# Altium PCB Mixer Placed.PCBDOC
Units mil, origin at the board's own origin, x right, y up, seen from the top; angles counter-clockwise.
Board outline 8000 x 4000 mil, 2 copper layers (Top Layer, Bottom Layer); 97 components, 56 nets, 281 pads, 0 vias.
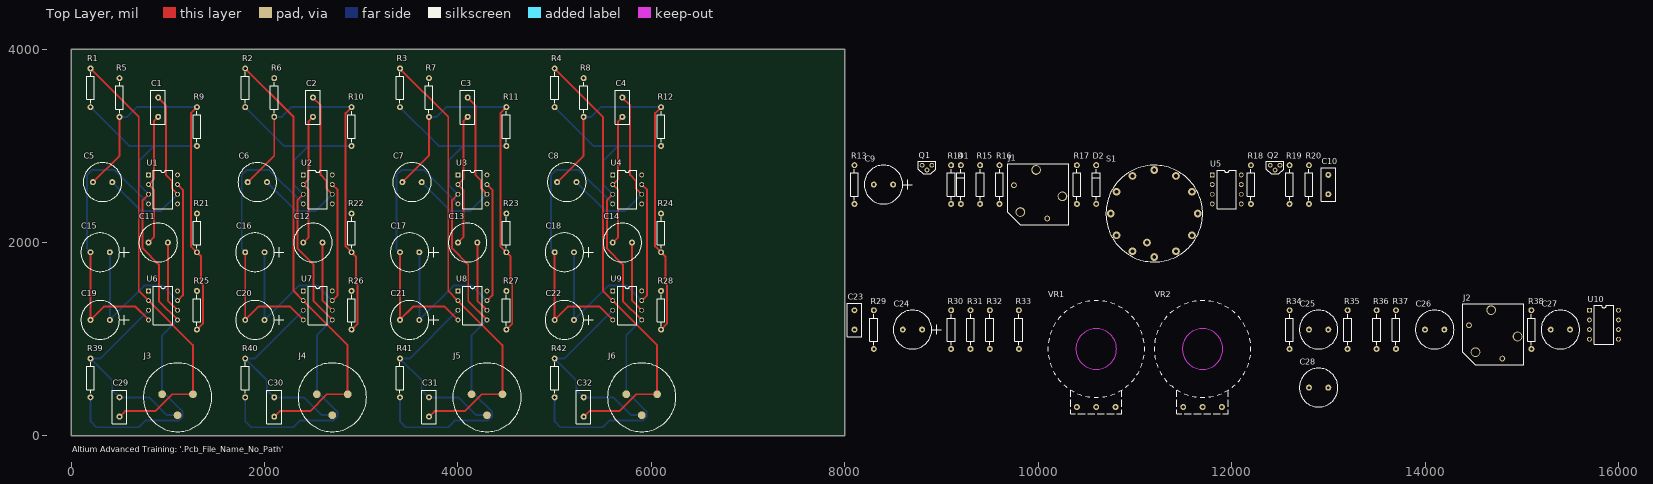
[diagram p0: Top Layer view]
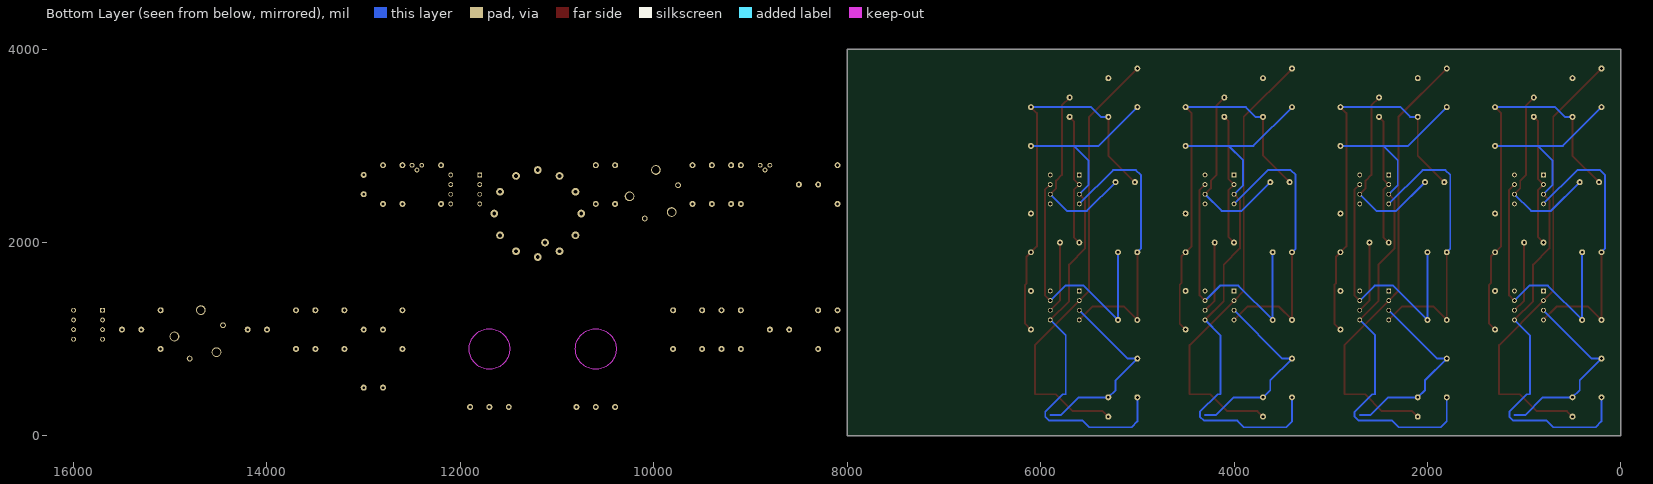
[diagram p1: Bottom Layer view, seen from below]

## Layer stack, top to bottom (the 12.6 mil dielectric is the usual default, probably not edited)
Top Solder: solder mask 0.4, Solder Resist, Dk 3.5
Top Layer: signal copper 1.4
Dielectric 1: dielectric 12.6, FR-4, Dk 4.8
Bottom Layer: signal copper 1.4
Bottom Solder: solder mask 0.4, Solder Resist, Dk 3.5

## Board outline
0,0 8000,0 8000,3000 8000,4000 0,4000 0,0

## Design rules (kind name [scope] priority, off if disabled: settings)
Clearance [All] p1: gap=20 ignorepadtopadclearanceinfootprint=FALSE except(0: Arc-Hole Track-Hole SMDPad-Hole THPad-Hole Via-Hole Fill-Hole Poly-Hole Region-Hole Text-Hole)
PolygonConnect [All] p1: connectstyle=Relief reliefconductorwidth=10 reliefentries=4 polygonreliefangle="90 Angle" airgapwidth=10
RoomDefinition INP4 [InComponentClass('INP4')] p1: confinementstyle=ConfineIn formatcopy=TRUE lockcomponents=FALSE outline 0,0 1500,0 1500,4000 0,4000
RoomDefinition INP3 [InComponentClass('INP3')] p2: confinementstyle=ConfineIn formatcopy=TRUE lockcomponents=FALSE outline 1600,0 3100,0 3100,4000 1600,4000
RoomDefinition INP2 [InComponentClass('INP2')] p3: confinementstyle=ConfineIn formatcopy=TRUE lockcomponents=FALSE outline 3200,0 4700,0 4700,4000 3200,4000
RoomDefinition HP [InComponentClass('HP')] p4: confinementstyle=ConfineIn formatcopy=TRUE lockcomponents=FALSE outline 8000,1700 13100,1700 13100,3000 8000,3000
RoomDefinition AUX [InComponentClass('AUX')] p5: confinementstyle=ConfineIn formatcopy=TRUE lockcomponents=FALSE outline 8000,100 16100,100 16100,1500 8000,1500
RoomDefinition INP1 [InComponentClass('INP1')] p6: confinementstyle=ConfineIn formatcopy=TRUE lockcomponents=FALSE outline 4800,0 6300,0 6300,4000 4800,4000
RoutingVias [All] p1: holewidth=28 width=50 viastyle="Through Hole" minholewidth=28 minwidth=50 maxholewidth=28 maxwidth=50
SilkToBoardRegionClearance [All] p1 off:
SilkToSilkClearance [All] p1 off: silktosilkclearance=50
SilkToSolderMaskClearance [IsPad] p1: minsilkscreentomaskgap=1 clearancetoexposedcopper=TRUE
SolderMaskExpansion [All] p1: expansion=4 istentingtop=FALSE
Width [All] p1: maxlimit=30 minlimit=10 preferedwidth=20
27 further rules are at their usual default settings.

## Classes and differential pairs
component class AUX: C23 C24 C25 C26 C27 C28 J2 R29 R30 R31 R32 R33 R34 R35 R36 R37 R38 U10 VR1 VR2
component class HP: C9 C10 D1 D2 J1 Q1 Q2 R13 R14 R15 R16 R17 R18 R19 R20 S1 U5
net class HEADPHONE[1..4]: HEADPHONE1 HEADPHONE2 HEADPHONE3 HEADPHONE4
net class MB[1..2]: MB1 MB2
component class INP1: C4 C8 C14 C18 C22 C32 J6 R4 R8 R12 R24 R28 R42 U4 U9
component class INP2: C1_INP2 C3 C5_INP2 C7 C11_INP2 C13 C15_INP2 C17 C19_INP2 C21 C29_INP2 C31 J3_INP2 J5 R1_INP2 R3 R5_INP2 R7 R9_INP2 R11 R21_INP2 R23 R25_INP2 R27 R39_INP2 R41 U1_INP2 U3 U6_INP2 U8
component class INP3: C1_INP3 C2 C5_INP3 C6 C11_INP3 C12 C15_INP3 C16 C19_INP3 C20 C29_INP3 C30 J3_INP3 J4 R1_INP3 R2 R5_INP3 R6 R9_INP3 R10 R21_INP3 R22 R25_INP3 R26 R39_INP3 R40 U1_INP3 U2 U6_INP3 U7
component class INP4: C1 C5 C11 C15 C19 C29 J3 R1 R5 R9 R21 R25 R39 U1 U6
channel class "Input channel": INP1 INP2 INP3 INP4

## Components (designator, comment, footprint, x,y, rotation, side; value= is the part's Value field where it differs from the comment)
C1 "10pF" RAD0.2 900,3300 r90 top
C2 "10pF" RAD0.2 2500,3300 r90 top (schematic designator C1)
C3 "10pF" RAD0.2 4100,3300 r90 top (schematic designator C1)
C4 "10pF" RAD0.2 5700,3300 r90 top (schematic designator C3)
C5 "2.2uF" RB.2/.4-NP 425,2625 r0 top
C6 "2.2uF" RB.2/.4-NP 2025,2625 r0 top (schematic designator C5)
C7 "2.2uF" RB.2/.4-NP 3625,2625 r0 top (schematic designator C5)
C8 "2.2uF" RB.2/.4-NP 5225,2625 r0 top (schematic designator C5)
C9 "10uF" RB.2/.4 8500,2600 r0 top (schematic designator C2)
C10 "22pF" RAD0.2 13000,2500 r90 top (schematic designator C1)
C11 "6.8uF" RB.2/.4-NP 1000,2000 r0 top
C12 "6.8uF" RB.2/.4-NP 2600,2000 r0 top (schematic designator C11)
C13 "6.8uF" RB.2/.4-NP 4200,2000 r0 top (schematic designator C11)
C14 "6.8uF" RB.2/.4-NP 5800,2000 r0 top (schematic designator C11)
C15 "10uF" RB.2/.4 400,1900 r0 top
C16 "10uF" RB.2/.4 2000,1900 r0 top (schematic designator C7)
C17 "10uF" RB.2/.4 3600,1900 r0 top (schematic designator C15)
C18 "10uF" RB.2/.4 5200,1900 r0 top (schematic designator C15)
C19 "10uF" RB.2/.4 400,1200 r0 top
C20 "10uF" RB.2/.4 2000,1200 r0 top (schematic designator C19)
C21 "10uF" RB.2/.4 3600,1200 r0 top (schematic designator C19)
C22 "10uF" RB.2/.4 5200,1200 r0 top (schematic designator C19)
C23 "270pF" RAD0.2 8100,1100 r90 top (schematic designator C14)
C24 "10uF" RB.2/.4 8800,1100 r0 top (schematic designator C13)
C25 "1uF" RB.2/.4-NP 13000,1100 r0 top (schematic designator C11)
C26 "2.2uF" RB.2/.4-NP 14200,1100 r0 top (schematic designator C10)
C27 "1uF" RB.2/.4-NP 15500,1100 r0 top (schematic designator C9)
C28 "2.2uF" RB.2/.4-NP 13000,500 r0 top (schematic designator C12)
C29 "270pF" RAD0.2 500,200 r90 top
C30 "270pF" RAD0.2 2100,200 r90 top (schematic designator C29)
C31 "270pF" RAD0.2 3700,200 r90 top (schematic designator C29)
C32 "270pF" RAD0.2 5300,200 r90 top (schematic designator C29)
D1 "1N914" DIODE0.4 9200,2400 r90 top (schematic designator D2)
D2 "1N914" DIODE0.4 10600,2400 r90 top (schematic designator D1)
J1 "Headphone" JACK-6.25MM 10000,2500 r0 top
J2 "Auxilary In" JACK-6.25MM 14706,1051 r0 top (schematic designator J3)
J3 "XLR" XLR-FEMALE 1100,400 r0 top
J4 "XLR" XLR-FEMALE 2700,400 r0 top (schematic designator J3)
J5 "XLR" XLR-FEMALE 4300,400 r0 top (schematic designator J3)
J6 "XLR" XLR-FEMALE 5900,400 r0 top (schematic designator J3)
Q1 "BC328-25" TO-92A 8800,2800 r0 top (schematic designator Q2)
Q2 "BC338-25" TO-92A 12400,2800 r0 top (schematic designator Q1)
R1 "10k" AXIAL0.4 200,3400 r90 top
R2 "10k" AXIAL0.4 1800,3400 r90 top (schematic designator R1)
R3 "10k" AXIAL0.4 3400,3400 r90 top (schematic designator R1)
R4 "10k" AXIAL0.4 5000,3400 r90 top (schematic designator R1)
R5 "15k" AXIAL0.4 500,3300 r90 top
R6 "15k" AXIAL0.4 2100,3300 r90 top (schematic designator R5)
R7 "15k" AXIAL0.4 3700,3300 r90 top (schematic designator R5)
R8 "15k" AXIAL0.4 5300,3300 r90 top (schematic designator R5)
R9 "10k" AXIAL0.4 1300,3000 r90 top
R10 "10k" AXIAL0.4 2900,3000 r90 top (schematic designator R9)
R11 "10k" AXIAL0.4 4500,3000 r90 top (schematic designator R9)
R12 "10k" AXIAL0.4 6100,3000 r90 top (schematic designator R9)
R13 "10k" AXIAL0.4 8100,2400 r90 top (schematic designator R8)
R14 "22k" AXIAL0.4 9100,2400 r90 top (schematic designator R7)
R15 "33R" AXIAL0.4 9400,2400 r90 top (schematic designator R6)
R16 "68R" AXIAL0.4 9600,2400 r90 top (schematic designator R5)
R17 "10k" AXIAL0.4 10400,2400 r90 top (schematic designator R4)
R18 "33R" AXIAL0.4 12200,2400 r90 top (schematic designator R3)
R19 "10k" AXIAL0.4 12600,2400 r90 top (schematic designator R2)
R20 "68k" AXIAL0.4 12800,2400 r90 top (schematic designator R1)
R21 "10k" AXIAL0.4 1300,1900 r90 top
R22 "10k" AXIAL0.4 2900,1900 r90 top (schematic designator R21)
R23 "10k" AXIAL0.4 4500,1900 r90 top (schematic designator R21)
R24 "10k" AXIAL0.4 6100,1900 r90 top (schematic designator R21)
R25 "15k" AXIAL0.4 1300,1100 r90 top
R26 "15k" AXIAL0.4 2900,1100 r90 top (schematic designator R25)
R27 "15k" AXIAL0.4 4500,1100 r90 top (schematic designator R25)
R28 "15k" AXIAL0.4 6100,1100 r90 top (schematic designator R25)
R29 "2.2k" AXIAL0.4 8300,900 r90 top (schematic designator R24)
R30 "6.8k" AXIAL0.4 9100,900 r90 top (schematic designator R23)
R31 "15k" AXIAL0.4 9300,900 r90 top (schematic designator R21)
R32 "15k" AXIAL0.4 9500,900 r90 top (schematic designator R22)
R33 "22k" AXIAL0.4 9800,900 r90 top (schematic designator R20)
R34 "10R" AXIAL0.4 12600,900 r90 top (schematic designator R19)
R35 "22k" AXIAL0.4 13200,900 r90 top (schematic designator R18)
R36 "15k" AXIAL0.4 13500,900 r90 top (schematic designator R16)
R37 "15k" AXIAL0.4 13700,900 r90 top (schematic designator R17)
R38 "10R" AXIAL0.4 15100,900 r90 top (schematic designator R15)
R39 "10k" AXIAL0.4 200,400 r90 top
R40 "10k" AXIAL0.4 1800,400 r90 top (schematic designator R39)
R41 "10k" AXIAL0.4 3400,400 r90 top (schematic designator R39)
R42 "10k" AXIAL0.4 5000,400 r90 top (schematic designator R39)
S1 "SW-12WAY" SW-12WAY 11200,2300 r0 top
U1 "OP27C" DIP8 800,2700 r0 top
U2 "OP27C" DIP8 2400,2700 r0 top (schematic designator U1)
U3 "OP27C" DIP8 4000,2700 r0 top (schematic designator U1)
U4 "OP27C" DIP8 5600,2700 r0 top (schematic designator U1)
U5 "TL071" DIP8 11800,2700 r0 top (schematic designator U1)
U6 "SSM2017P (8)" DIP8 800,1500 r0 top
U7 "SSM2017P (8)" DIP8 2400,1500 r0 top (schematic designator U6)
U8 "SSM2017P (8)" DIP8 4000,1500 r0 top (schematic designator U6)
U9 "SSM2017P (8)" DIP8 5600,1500 r0 top (schematic designator U6)
U10 "LM833M" DIP8 15700,1300 r0 top (schematic designator U4)
VR1 "10k LIN" "POT - 24MM" 10600,900 r0 top (schematic designator VR2)
VR2 "10k LOG" "POT - 24MM" 11700,900 r0 top (schematic designator VR1)

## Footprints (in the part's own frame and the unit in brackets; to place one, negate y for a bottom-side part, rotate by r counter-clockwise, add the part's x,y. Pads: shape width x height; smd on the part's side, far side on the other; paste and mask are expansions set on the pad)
AXIAL0.4 [mil]
  round 62 hole 32: 1(0,0) 2(400,0)
  silkscreen extent 40,-40 360,40
DIODE0.4 [mil]
  round 62 hole 32: 1(0,0) 2(400,0)
  silkscreen extent 40,-40 360,40
DIP8 [mil]
  rect 50x50 hole 32: 1(0,0)
  round 50 hole 32: 2(0,-100) 3(0,-200) 4(0,-300) 5(300,-300) 6(300,-200) 7(300,-100) 8(300,0)
  silkscreen extent 50,-350 250,50
JACK-6.25MM [mil]
  round 60 hole 39: 0(-251,94) 0(94,-251)
  round 100 hole 78: 1(251,-22) 2(-22,251) 3(-184,-184)
  silkscreen extent -315,-315 315,315
"POT - 24MM" [mil]
  round 62 hole 35: 1(-200,-600) 2(0,-600) 3(200,-600)
  round 50 hole 236.22 unplated mask+4: MNT(0,0)
  Keep-Out Layer circle w10: c0,0 r210
  silkscreen extent -500,-670 500,500
RAD0.2 [mil]
  round 62 hole 28: 1(0,0) 2(200,0)
  silkscreen extent -75,-75 275,75
RB.2/.4 [mil]
  round 62 hole 28: 1(0,0) 2(-200,0)
  silkscreen extent -300,-200 200,200
RB.2/.4-NP [mil]
  round 62 hole 28: 1(0,0) 2(-200,0)
  silkscreen extent -300,-200 100,200
SW-12WAY [mil]
  round 80 hole 40: 1(225,389.71) 2(389.71,225) 3(450,0) 4(389.71,-225) 5(225,-389.71) 6(0,-450) 7(-225,-389.71) 8(-389.71,-225) 9(-450,0) 10(-389.71,225) 11(-225,389.71) 12(0,450) 13(-75,-300)
  silkscreen extent -500,-500 500,500
TO-92A [mil]
  round 50 hole 30: 1(0,0) 2(50,-50) 3(100,0)
  silkscreen extent -40,-90 140,40
XLR-FEMALE [mm]
  round 2.032 smd: 1(-4.05,0.8) 2(4.05,0.8) 3(0,-4.7)
  silkscreen extent -9,-9 9,9

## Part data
C1 C2 C3 C4 C5 C6 C7 C8 C10 C11 C12 C13 C14 C23 C25 C26 C27 C28 C29 C30 C31 C32: library part CAP, "Capacitor"
C9 C15 C16 C17 C18 C19 C20 C21 C22 C24: library part "CAPACITOR POL", "Bi-Polar Capacitor"
D1 D2: "Diode"
J1 J2: library part "PHONEJACK MONO"
J3 J4 J5 J6: "XLR connector, PCB mounted"
Q1: "PNP BJT"
Q2: "NPN BJT"
R1 R2 R3 R4 R5 R6 R7 R8 R9 R10 R11 R12 R13 R14 R15 R16 R17 R18 R19 R20 R21 R22 R23 R24 R25 R26 R27 R28 R29 R30 R31 R32 R33 R34 R35 R36 R37 R38 R39 R40 R41 R42: library part RES1, "Resistor"
U1 U2 U3 U4: "Low Noise, High Speed Precision Operational Amplifier"
U5: "Low-Noise  JFET-Input Operational Amplifiers"
U6 U7 U8 U9: "Self-Contained Audio Preamplifier"
U10: "Fast Settling Dual Operational Amplifier"
VR1 VR2: library part POT1, "Potentiometer"

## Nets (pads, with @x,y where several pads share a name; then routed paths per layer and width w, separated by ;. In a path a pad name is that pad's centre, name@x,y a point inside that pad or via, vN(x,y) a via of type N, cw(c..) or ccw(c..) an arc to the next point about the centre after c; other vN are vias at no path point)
+15V: C9.1 C15.1 C16.1 C17.1 C18.1 C19.1 C20.1 C21.1 C22.1 C24.1 Q2.1 R19.2 U1.7 U2.7 U3.7 U4.7 U5.7 U6.7 U7.7 U8.7 U9.7 U10.4 | length 11427.2
  Top Layer w20: U6.7 1155,1455 1155,2545 U1.7 ; U7.7 2755,1455 2755,2545 U2.7 ; U8.7 4355,1455 4355,2545 U3.7 ; U9.7 5955,1455 5955,2545 U4.7
  Bottom Layer w20: C15.1 C19.1 755,1555 945,1555 U6.7 ; C16.1 C20.1 2355,1555 2545,1555 U7.7 ; C17.1 C21.1 3955,1555 4145,1555 U8.7 ; C18.1 C22.1 5555,1555 5745,1555 U9.7
-15V: C9.2 C15.2 C16.2 C17.2 C18.2 C19.2 C20.2 C21.2 C22.2 C24.2 Q1.1 R13.1 U1.4 U2.4 U3.4 U4.4 U5.4 U6.4 U7.4 U8.4 U9.4 U10.8 | length 12130.3
  Top Layer w20: C15.2 C19.2 340,1340 660,1340 U6.4 ; C16.2 C20.2 1940,1340 2260,1340 U7.4 ; C17.2 C21.2 3540,1340 3860,1340 U8.4 ; C18.2 C22.2 5140,1340 5460,1340 U9.4
  Bottom Layer w20: C15.2 164,1936 164,2700 214,2750 450,2750 U1.4 ; C16.2 1764,1936 1764,2700 1814,2750 2050,2750 U2.4 ; C17.2 3364,1936 3364,2700 3414,2750 3650,2750 U3.4 ; C18.2 4964,1936 4964,2700 5014,2750 5250,2750 U4.4
GND: J1.3 J2.3 J3.1 J4.1 J5.1 J6.1 R1.1 R2.1 R3.1 R4.1 R9.1 R10.1 R11.1 R12.1 R14.1 R29.2 R33.1 R35.1 R39.1 R40.1 R41.1 R42.1 U1.3 U2.3 U3.3 U4.3 U6.5 U7.5 U8.5 U9.5 VR1.2 VR2.3 | length 23140.7
  Top Layer w20: U1.3 739,2439 739,1939 906,1772 906,1394 U6.5 ; U2.3 2339,2439 2339,1939 2506,1772 2506,1394 U7.5 ; U3.3 3939,2439 3939,1939 4106,1772 4106,1394 U8.5 ; U4.3 5539,2439 5539,1939 5706,1772 5706,1394 U9.5
  Bottom Layer w20: R39.1 200,150 260,90 698,90 766,158 1110,158 1152,200 1152,250 970.5,431.5 940.55,431.5 940,432.05 940,1040 U6.5 ; R1.1 600,3000 857,3000 ; U1.3 707,2593 707,2850 857,3000 ; R9.1 857,3000 ; R40.1 1800,150 1860,90 2298,90 2366,158 2710,158 2752,200 2752,250 2570.5,431.5 2540.55,431.5 2540,432.05 2540,1040 U7.5 ; R2.1 2200,3000 2457,3000 ; U2.3 2307,2593 2307,2850 2457,3000 ; R10.1 2457,3000 ; R41.1 3400,150 3460,90 3898,90 3966,158 4310,158 4352,200 4352,250 4170.5,431.5 4140.55,431.5 4140,432.05 4140,1040 U8.5 ; R3.1 3800,3000 4057,3000 ; U3.3 3907,2593 3907,2850 4057,3000 ; R11.1 4057,3000 ; R42.1 5000,150 5060,90 5498,90 5566,158 5910,158 5952,200 5952,250 5770.5,431.5 5740.55,431.5 5740,432.05 5740,1040 U9.5 ; R4.1 5400,3000 5657,3000 ; U4.3 5507,2593 5507,2850 5657,3000 ; R12.1 5657,3000
HEADPHONE1: R24.2 S1.8
HEADPHONE2: R23.2 S1.7
HEADPHONE3: R22.2 S1.6
HEADPHONE4: R21.2 S1.5
MB1: R5.2 R6.2 R7.2 R8.2 R37.2 S1.11
MB2: R25.2 R26.2 R27.2 R28.2 R32.2 S1.12
NetC1_1: C1.1 C11.2 U1.2 | length 1387
  Top Layer w20: C11.2 855,2055 855,2545 U1.2 855,2655 855,3255 C1.1
NetC1_2: C1.2 C5.1 U1.6 | length 1952.1
  Top Layer w20: C1.2 980,3420 980,2700 1040,2640 1040,2560 U1.6
  Bottom Layer w20: C5.1 722,2328 928,2328 U1.6
NetC2_1: C2.1 C12.2 U2.2 | length 1387
  Top Layer w20: C12.2 2455,2055 2455,2545 U2.2 2455,2655 2455,3255 C2.1
NetC2_2: C2.2 C6.1 U2.6 | length 1952.1
  Top Layer w20: C2.2 2580,3420 2580,2700 2640,2640 2640,2560 U2.6
  Bottom Layer w20: C6.1 2322,2328 2528,2328 U2.6
NetC3_1: C3.1 C13.2 U3.2 | length 1387
  Top Layer w20: C13.2 4055,2055 4055,2545 U3.2 4055,2655 4055,3255 C3.1
NetC3_2: C3.2 C7.1 U3.6 | length 1952.1
  Top Layer w20: C3.2 4180,3420 4180,2700 4240,2640 4240,2560 U3.6
  Bottom Layer w20: C7.1 3922,2328 4128,2328 U3.6
NetC4_1: C4.1 C14.2 U4.2 | length 1387
  Top Layer w20: C14.2 5655,2055 5655,2545 U4.2 5655,2655 5655,3255 C4.1
NetC4_2: C4.2 C8.1 U4.6 | length 1952.1
  Top Layer w20: C4.2 5780,3420 5780,2700 5840,2640 5840,2560 U4.6
  Bottom Layer w20: C8.1 5522,2328 5728,2328 U4.6
NetC5_2: C5.2 R5.1 R9.2 R21.1 R25.1 | length 4031.4
  Top Layer w20: C5.2 500,2900 R5.1 ; R25.1 1361,1161 1361,1564 1344,1581 1344,1856 R21.1 1239,1961 1239,3339 R9.2
  Bottom Layer w20: R5.1 578,3300 678,3400 R9.2
NetC6_2: C6.2 R6.1 R10.2 R22.1 R26.1 | length 4031.4
  Top Layer w20: C6.2 2100,2900 R6.1 ; R26.1 2961,1161 2961,1564 2944,1581 2944,1856 R22.1 2839,1961 2839,3339 R10.2
  Bottom Layer w20: R6.1 2178,3300 2278,3400 R10.2
NetC7_2: C7.2 R7.1 R11.2 R23.1 R27.1 | length 4031.4
  Top Layer w20: C7.2 3700,2900 R7.1 ; R27.1 4561,1161 4561,1564 4544,1581 4544,1856 R23.1 4439,1961 4439,3339 R11.2
  Bottom Layer w20: R7.1 3778,3300 3878,3400 R11.2
NetC8_2: C8.2 R8.1 R12.2 R24.1 R28.1 | length 4031.4
  Top Layer w20: C8.2 5300,2900 R8.1 ; R28.1 6161,1161 6161,1564 6144,1581 6144,1856 R24.1 6039,1961 6039,3339 R12.2
  Bottom Layer w20: R8.1 5378,3300 5478,3400 R12.2
NetC10_1: C10.1 R17.2 R20.1 U5.2
NetC10_2: C10.2 R15.2 R16.1 R18.1 R20.2
NetC11_1: C11.1 U6.6 | length 741.4
  Top Layer w20: C11.1 1000,1400 U6.6
NetC12_1: C12.1 U7.6 | length 741.4
  Top Layer w20: C12.1 2600,1400 U7.6
NetC13_1: C13.1 U8.6 | length 741.4
  Top Layer w20: C13.1 4200,1400 U8.6
NetC14_1: C14.1 U9.6 | length 741.4
  Top Layer w20: C14.1 5800,1400 U9.6
NetC23_1: C23.1 R29.1 R30.2 U10.6
NetC23_2: C23.2 C28.1 R30.1 U10.7
NetC25_1: C25.1 VR2.2
NetC25_2: C25.2 R33.2 R34.1
NetC26_1: C26.1 U10.1 U10.2
NetC26_2: C26.2 VR2.1
NetC27_1: C27.1 J2.1
NetC27_2: C27.2 R35.2 R38.1
NetC28_2: C28.2 R31.1 R36.1
NetC29_1: C29.1 J3.2 R1.2 U6.2 | length 4662.7
  Top Layer w20: R1.2 699,3301 699,1501 U6.2 1259.45,940.55 J3.2 1043.5,431.5 870,258 558,258 C29.1
NetC29_2: C29.2 J3.3 R39.2 U6.3 | length 2008
  Bottom Layer w20: U6.3 300,800 R39.2 425,575 425,475 C29.2 804.96,400 990,214.96 1100,214.96
NetC30_1: C30.1 J4.2 R2.2 U7.2 | length 4662.7
  Top Layer w20: R2.2 2299,3301 2299,1501 U7.2 2859.45,940.55 J4.2 2643.5,431.5 2470,258 2158,258 C30.1
NetC30_2: C30.2 J4.3 R40.2 U7.3 | length 2008
  Bottom Layer w20: U7.3 1900,800 R40.2 2025,575 2025,475 C30.2 2404.96,400 2590,214.96 2700,214.96
NetC31_1: C31.1 J5.2 R3.2 U8.2 | length 4662.7
  Top Layer w20: R3.2 3899,3301 3899,1501 U8.2 4459.45,940.55 J5.2 4243.5,431.5 4070,258 3758,258 C31.1
NetC31_2: C31.2 J5.3 R41.2 U8.3 | length 2008
  Bottom Layer w20: U8.3 3500,800 R41.2 3625,575 3625,475 C31.2 4004.96,400 4190,214.96 4300,214.96
NetC32_1: C32.1 J6.2 R4.2 U9.2 | length 4662.7
  Top Layer w20: R4.2 5499,3301 5499,1501 U9.2 6059.45,940.55 J6.2 5843.5,431.5 5670,258 5358,258 C32.1
NetC32_2: C32.2 J6.3 R42.2 U9.3 | length 2008
  Bottom Layer w20: U9.3 5100,800 R42.2 5225,575 5225,475 C32.2 5604.96,400 5790,214.96 5900,214.96
NetD1_1: D1.1 D2.2 U5.6
NetD1_2: D1.2 Q1.2 R13.2
NetD2_1: D2.1 Q2.2 R19.1
NetJ1_1: J1.1 R16.2
NetQ1_3: Q1.3 R15.1
NetQ2_3: Q2.3 R18.2
NetR14_2: R14.2 U5.3
NetR17_1: R17.1 S1.13
NetR31_2: R31.2 R32.1 VR1.3
NetR34_2: R34.2 U10.5
NetR36_2: R36.2 R37.1 VR1.1
NetR38_2: R38.2 U10.3
pads on no net: J1.0 J1.2 J2.0 J2.2 S1.1 S1.2 S1.3 S1.4 S1.9 S1.10 U1.1 U1.5 U1.8 U2.1 U2.5 U2.8 U3.1 U3.5 U3.8 U4.1 U4.5 U4.8 U5.1 U5.5 U5.8 U6.1 U6.8 U7.1 U7.8 U8.1 U8.8 U9.1 U9.8 VR1.MNT VR2.MNT

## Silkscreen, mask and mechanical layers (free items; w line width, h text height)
Top Overlay:
  text "Altium Advanced Training: '.Pcb_File_Name_No_Path'" at 10,-170.01 h60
